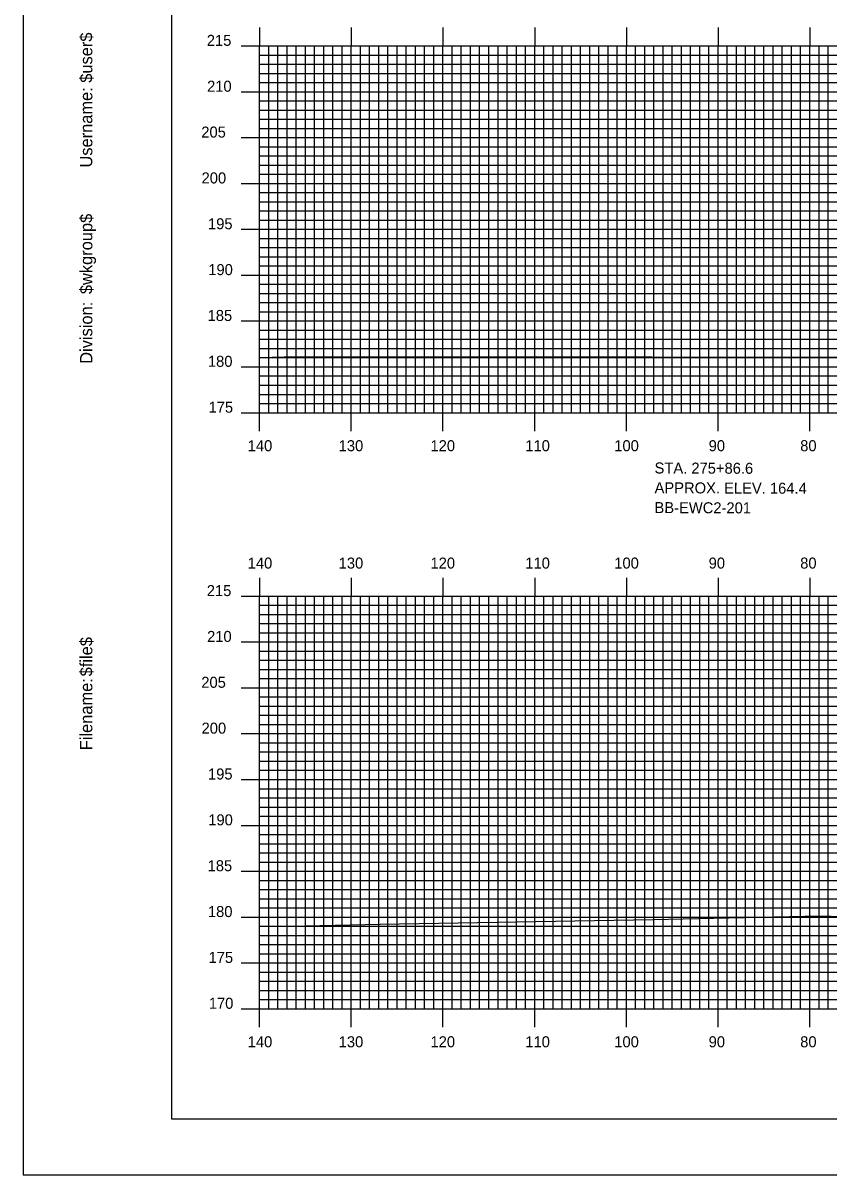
# Model space of a CAD drawing. Extents: x 1809800 to 1810143, y 442591 to 442811.
# Drawn here: x 1809799.6 to 1809887.4, y 442590.5 to 442716.2 of the extents above; entities that cross this region are included whole.
import ezdxf

# ---------------------------------------------------------------- set-up
doc = ezdxf.new("R2010")
doc.units = 0
for name, color, linetype in [('BORDER', 7, 'Continuous'), ('BORING - NO REFUSAL', 7, 'Continuous'), ('H_V ANNOTATION', 7, 'Continuous'), ('MAJOR', 7, 'Continuous'), ('MINOR', 7, 'Continuous'), ('PLOT BOUNDARY', 7, 'Continuous'), ('S_Roadway_Centerline', 7, 'Continuous')]:
    doc.layers.add(name, color=color, linetype=linetype)

msp = doc.modelspace()

# ---------------------------------------------------------------- linework, layer by layer
at = {"layer": 'BORDER'}
msp.add_lwpolyline([(1809815.75, 442596.67), (1810135.75, 442596.67), (1810135.75, 442806.67), (1809815.75, 442806.67)], close=True, dxfattribs=at)
at = {"layer": 'MAJOR'}
for p, q in [((1809825.35, 442715.67), (1809825.35, 442713.67)), ((1809835.35, 442715.67), (1809835.35, 442713.67)), ((1809845.35, 442715.67), (1809845.35, 442713.67)), ((1809855.35, 442715.67), (1809855.35, 442713.67)), ((1809865.35, 442715.67), (1809865.35, 442713.67)), ((1809875.35, 442715.67), (1809875.35, 442713.67)), ((1809885.35, 442715.67), (1809885.35, 442713.67)), ((1809823.35, 442713.67), (1809825.35, 442713.67)), ((1809825.35, 442713.67), (1810105.35, 442713.67)), ((1809825.35, 442673.67), (1809825.35, 442713.67)), ((1809825.35, 442673.67), (1809825.35, 442713.67)), ((1809825.35, 442713.67), (1810105.35, 442713.67)), ((1809835.35, 442673.67), (1809835.35, 442713.67)), ((1809845.35, 442673.67), (1809845.35, 442713.67)), ((1809855.35, 442673.67), (1809855.35, 442713.67)), ((1809865.35, 442673.67), (1809865.35, 442713.67)), ((1809875.35, 442673.67), (1809875.35, 442713.67)), ((1809885.35, 442673.67), (1809885.35, 442713.67)), ((1809823.35, 442708.67), (1809825.35, 442708.67)), ((1809825.35, 442708.67), (1810105.35, 442708.67)), ((1809823.35, 442703.67), (1809825.35, 442703.67)), ((1809825.35, 442703.67), (1810105.35, 442703.67)), ((1809823.35, 442698.67), (1809825.35, 442698.67)), ((1809825.35, 442698.67), (1810105.35, 442698.67)), ((1809823.35, 442693.67), (1809825.35, 442693.67)), ((1809825.35, 442693.67), (1810105.35, 442693.67)), ((1809823.35, 442688.67), (1809825.35, 442688.67)), ((1809825.35, 442688.67), (1810105.35, 442688.67)), ((1809823.35, 442683.67), (1809825.35, 442683.67)), ((1809825.35, 442683.67), (1810105.35, 442683.67)), ((1809823.35, 442678.67), (1809825.35, 442678.67)), ((1809825.35, 442678.67), (1810105.35, 442678.67)), ((1809823.35, 442673.67), (1809825.35, 442673.67)), ((1809825.35, 442673.67), (1810105.35, 442673.67)), ((1809825.35, 442673.67), (1810105.35, 442673.67)), ((1809825.35, 442671.66), (1809825.35, 442673.67)), ((1809835.35, 442671.66), (1809835.35, 442673.67)), ((1809845.35, 442671.66), (1809845.35, 442673.67)), ((1809855.35, 442671.66), (1809855.35, 442673.67)), ((1809865.35, 442671.66), (1809865.35, 442673.67)), ((1809875.35, 442671.66), (1809875.35, 442673.67)), ((1809885.35, 442671.66), (1809885.35, 442673.67)), ((1809825.35, 442655.67), (1809825.35, 442653.67)), ((1809835.35, 442655.67), (1809835.35, 442653.67)), ((1809845.35, 442655.67), (1809845.35, 442653.67)), ((1809855.35, 442655.67), (1809855.35, 442653.67)), ((1809865.35, 442655.67), (1809865.35, 442653.67)), ((1809875.35, 442655.67), (1809875.35, 442653.67)), ((1809885.35, 442655.67), (1809885.35, 442653.67)), ((1809823.35, 442653.67), (1809825.35, 442653.67)), ((1809825.35, 442653.67), (1810105.35, 442653.67)), ((1809825.35, 442608.67), (1809825.35, 442653.67)), ((1809825.35, 442608.67), (1809825.35, 442653.67)), ((1809825.35, 442653.67), (1810105.35, 442653.67)), ((1809835.35, 442608.67), (1809835.35, 442653.67)), ((1809845.35, 442608.67), (1809845.35, 442653.67)), ((1809855.35, 442608.67), (1809855.35, 442653.67)), ((1809865.35, 442608.67), (1809865.35, 442653.67)), ((1809875.35, 442608.67), (1809875.35, 442653.67)), ((1809885.35, 442608.67), (1809885.35, 442653.67)), ((1809823.35, 442648.67), (1809825.35, 442648.67)), ((1809825.35, 442648.67), (1810105.35, 442648.67)), ((1809823.35, 442643.67), (1809825.35, 442643.67)), ((1809825.35, 442643.67), (1810105.35, 442643.67)), ((1809823.35, 442638.67), (1809825.35, 442638.67)), ((1809825.35, 442638.67), (1810105.35, 442638.67)), ((1809823.35, 442633.67), (1809825.35, 442633.67)), ((1809825.35, 442633.67), (1810105.35, 442633.67)), ((1809823.35, 442628.67), (1809825.35, 442628.67)), ((1809825.35, 442628.67), (1810105.35, 442628.67)), ((1809823.35, 442623.67), (1809825.35, 442623.67)), ((1809825.35, 442623.67), (1810105.35, 442623.67)), ((1809823.35, 442618.67), (1809825.35, 442618.67)), ((1809825.35, 442618.67), (1810105.35, 442618.67)), ((1809823.35, 442613.67), (1809825.35, 442613.67)), ((1809825.35, 442613.67), (1810105.35, 442613.67)), ((1809823.35, 442608.67), (1809825.35, 442608.67)), ((1809825.35, 442608.67), (1810105.35, 442608.67)), ((1809825.35, 442608.67), (1810105.35, 442608.67)), ((1809825.35, 442606.66), (1809825.35, 442608.67)), ((1809835.35, 442606.66), (1809835.35, 442608.67)), ((1809845.35, 442606.66), (1809845.35, 442608.67)), ((1809855.35, 442606.66), (1809855.35, 442608.67)), ((1809865.35, 442606.66), (1809865.35, 442608.67)), ((1809875.35, 442606.66), (1809875.35, 442608.67)), ((1809885.35, 442606.66), (1809885.35, 442608.67))]:
    msp.add_line(p, q, dxfattribs=at)
at = {"layer": 'MINOR'}
for p, q in [((1809826.35, 442673.67), (1809826.35, 442713.67)), ((1809827.35, 442673.67), (1809827.35, 442713.67)), ((1809828.35, 442673.67), (1809828.35, 442713.67)), ((1809829.35, 442673.67), (1809829.35, 442713.67)), ((1809830.35, 442673.67), (1809830.35, 442713.67)), ((1809831.35, 442673.67), (1809831.35, 442713.67)), ((1809832.35, 442673.67), (1809832.35, 442713.67)), ((1809833.35, 442673.67), (1809833.35, 442713.67)), ((1809834.35, 442673.67), (1809834.35, 442713.67)), ((1809836.35, 442673.67), (1809836.35, 442713.67)), ((1809837.35, 442673.67), (1809837.35, 442713.67)), ((1809838.35, 442673.67), (1809838.35, 442713.67)), ((1809839.35, 442673.67), (1809839.35, 442713.67)), ((1809840.35, 442673.67), (1809840.35, 442713.67)), ((1809841.35, 442673.67), (1809841.35, 442713.67)), ((1809842.35, 442673.67), (1809842.35, 442713.67)), ((1809843.35, 442673.67), (1809843.35, 442713.67)), ((1809844.35, 442673.67), (1809844.35, 442713.67)), ((1809846.35, 442673.67), (1809846.35, 442713.67)), ((1809847.35, 442673.67), (1809847.35, 442713.67)), ((1809848.35, 442673.67), (1809848.35, 442713.67)), ((1809849.35, 442673.67), (1809849.35, 442713.67)), ((1809850.35, 442673.67), (1809850.35, 442713.67)), ((1809851.35, 442673.67), (1809851.35, 442713.67)), ((1809852.35, 442673.67), (1809852.35, 442713.67)), ((1809853.35, 442673.67), (1809853.35, 442713.67)), ((1809854.35, 442673.67), (1809854.35, 442713.67)), ((1809856.35, 442673.67), (1809856.35, 442713.67)), ((1809857.35, 442673.67), (1809857.35, 442713.67)), ((1809858.35, 442673.67), (1809858.35, 442713.67)), ((1809859.35, 442673.67), (1809859.35, 442713.67)), ((1809860.35, 442673.67), (1809860.35, 442713.67)), ((1809861.35, 442673.67), (1809861.35, 442713.67)), ((1809862.35, 442673.67), (1809862.35, 442713.67)), ((1809863.35, 442673.67), (1809863.35, 442713.67)), ((1809864.35, 442673.67), (1809864.35, 442713.67)), ((1809866.35, 442673.67), (1809866.35, 442713.67)), ((1809867.35, 442673.67), (1809867.35, 442713.67)), ((1809868.35, 442673.67), (1809868.35, 442713.67)), ((1809869.35, 442673.67), (1809869.35, 442713.67)), ((1809870.35, 442673.67), (1809870.35, 442713.67)), ((1809871.35, 442673.67), (1809871.35, 442713.67)), ((1809872.35, 442673.67), (1809872.35, 442713.67)), ((1809873.35, 442673.67), (1809873.35, 442713.67)), ((1809874.35, 442673.67), (1809874.35, 442713.67)), ((1809876.35, 442673.67), (1809876.35, 442713.67)), ((1809877.35, 442673.67), (1809877.35, 442713.67)), ((1809878.35, 442673.67), (1809878.35, 442713.67)), ((1809879.35, 442673.67), (1809879.35, 442713.67)), ((1809880.35, 442673.67), (1809880.35, 442713.67)), ((1809881.35, 442673.67), (1809881.35, 442713.67)), ((1809882.35, 442673.67), (1809882.35, 442713.67)), ((1809883.35, 442673.67), (1809883.35, 442713.67)), ((1809884.35, 442673.67), (1809884.35, 442713.67)), ((1809886.35, 442673.67), (1809886.35, 442713.67)), ((1809887.35, 442673.67), (1809887.35, 442713.67)), ((1809825.35, 442712.67), (1810105.35, 442712.67)), ((1809825.35, 442712.67), (1809827.35, 442712.67)), ((1809825.35, 442711.67), (1810105.35, 442711.67)), ((1809825.35, 442711.67), (1809827.35, 442711.67)), ((1809825.35, 442710.67), (1810105.35, 442710.67)), ((1809825.35, 442710.67), (1809827.35, 442710.67)), ((1809825.35, 442709.67), (1810105.35, 442709.67)), ((1809825.35, 442709.67), (1809827.35, 442709.67)), ((1809825.35, 442707.67), (1810105.35, 442707.67)), ((1809825.35, 442707.67), (1809827.35, 442707.67)), ((1809825.35, 442706.67), (1810105.35, 442706.67)), ((1809825.35, 442706.67), (1809827.35, 442706.67)), ((1809825.35, 442705.67), (1810105.35, 442705.67)), ((1809825.35, 442705.67), (1809827.35, 442705.67)), ((1809825.35, 442704.67), (1810105.35, 442704.67)), ((1809825.35, 442704.67), (1809827.35, 442704.67)), ((1809825.35, 442702.67), (1810105.35, 442702.67)), ((1809825.35, 442702.67), (1809827.35, 442702.67)), ((1809825.35, 442701.67), (1810105.35, 442701.67)), ((1809825.35, 442701.67), (1809827.35, 442701.67)), ((1809825.35, 442700.67), (1810105.35, 442700.67)), ((1809825.35, 442700.67), (1809827.35, 442700.67)), ((1809825.35, 442699.67), (1810105.35, 442699.67)), ((1809825.35, 442699.67), (1809827.35, 442699.67)), ((1809825.35, 442697.67), (1810105.35, 442697.67)), ((1809825.35, 442697.67), (1809827.35, 442697.67)), ((1809825.35, 442696.67), (1810105.35, 442696.67)), ((1809825.35, 442696.67), (1809827.35, 442696.67)), ((1809825.35, 442695.67), (1810105.35, 442695.67)), ((1809825.35, 442695.67), (1809827.35, 442695.67)), ((1809825.35, 442694.67), (1810105.35, 442694.67)), ((1809825.35, 442694.67), (1809827.35, 442694.67)), ((1809825.35, 442692.67), (1810105.35, 442692.67)), ((1809825.35, 442692.67), (1809827.35, 442692.67)), ((1809825.35, 442691.67), (1810105.35, 442691.67)), ((1809825.35, 442691.67), (1809827.35, 442691.67)), ((1809825.35, 442690.67), (1810105.35, 442690.67)), ((1809825.35, 442690.67), (1809827.35, 442690.67)), ((1809825.35, 442689.67), (1810105.35, 442689.67)), ((1809825.35, 442689.67), (1809827.35, 442689.67)), ((1809825.35, 442687.67), (1810105.35, 442687.67)), ((1809825.35, 442687.67), (1809827.35, 442687.67)), ((1809825.35, 442686.67), (1810105.35, 442686.67)), ((1809825.35, 442686.67), (1809827.35, 442686.67)), ((1809825.35, 442685.67), (1810105.35, 442685.67)), ((1809825.35, 442685.67), (1809827.35, 442685.67)), ((1809825.35, 442684.67), (1810105.35, 442684.67)), ((1809825.35, 442684.67), (1809827.35, 442684.67)), ((1809825.35, 442682.67), (1810105.35, 442682.67)), ((1809825.35, 442682.67), (1809827.35, 442682.67)), ((1809825.35, 442681.67), (1810105.35, 442681.67)), ((1809825.35, 442681.67), (1809827.35, 442681.67)), ((1809825.35, 442680.67), (1810105.35, 442680.67)), ((1809825.35, 442680.67), (1809827.35, 442680.67)), ((1809825.35, 442679.67), (1810105.35, 442679.67)), ((1809825.35, 442679.67), (1809827.35, 442679.67)), ((1809825.35, 442677.67), (1810105.35, 442677.67)), ((1809825.35, 442677.67), (1809827.35, 442677.67)), ((1809825.35, 442676.67), (1810105.35, 442676.67)), ((1809825.35, 442676.67), (1809827.35, 442676.67)), ((1809825.35, 442675.67), (1810105.35, 442675.67)), ((1809825.35, 442675.67), (1809827.35, 442675.67)), ((1809825.35, 442674.67), (1810105.35, 442674.67)), ((1809825.35, 442674.67), (1809827.35, 442674.67)), ((1809826.35, 442608.67), (1809826.35, 442653.67)), ((1809827.35, 442608.67), (1809827.35, 442653.67)), ((1809828.35, 442608.67), (1809828.35, 442653.67)), ((1809829.35, 442608.67), (1809829.35, 442653.67)), ((1809830.35, 442608.67), (1809830.35, 442653.67)), ((1809831.35, 442608.67), (1809831.35, 442653.67)), ((1809832.35, 442608.67), (1809832.35, 442653.67)), ((1809833.35, 442608.67), (1809833.35, 442653.67)), ((1809834.35, 442608.67), (1809834.35, 442653.67)), ((1809836.35, 442608.67), (1809836.35, 442653.67)), ((1809837.35, 442608.67), (1809837.35, 442653.67)), ((1809838.35, 442608.67), (1809838.35, 442653.67)), ((1809839.35, 442608.67), (1809839.35, 442653.67)), ((1809840.35, 442608.67), (1809840.35, 442653.67)), ((1809841.35, 442608.67), (1809841.35, 442653.67)), ((1809842.35, 442608.67), (1809842.35, 442653.67)), ((1809843.35, 442608.67), (1809843.35, 442653.67)), ((1809844.35, 442608.67), (1809844.35, 442653.67)), ((1809846.35, 442608.67), (1809846.35, 442653.67)), ((1809847.35, 442608.67), (1809847.35, 442653.67)), ((1809848.35, 442608.67), (1809848.35, 442653.67)), ((1809849.35, 442608.67), (1809849.35, 442653.67)), ((1809850.35, 442608.67), (1809850.35, 442653.67)), ((1809851.35, 442608.67), (1809851.35, 442653.67)), ((1809852.35, 442608.67), (1809852.35, 442653.67)), ((1809853.35, 442608.67), (1809853.35, 442653.67)), ((1809854.35, 442608.67), (1809854.35, 442653.67)), ((1809856.35, 442608.67), (1809856.35, 442653.67)), ((1809857.35, 442608.67), (1809857.35, 442653.67)), ((1809858.35, 442608.67), (1809858.35, 442653.67)), ((1809859.35, 442608.67), (1809859.35, 442653.67)), ((1809860.35, 442608.67), (1809860.35, 442653.67)), ((1809861.35, 442608.67), (1809861.35, 442653.67)), ((1809862.35, 442608.67), (1809862.35, 442653.67)), ((1809863.35, 442608.67), (1809863.35, 442653.67)), ((1809864.35, 442608.67), (1809864.35, 442653.67)), ((1809866.35, 442608.67), (1809866.35, 442653.67)), ((1809867.35, 442608.67), (1809867.35, 442653.67)), ((1809868.35, 442608.67), (1809868.35, 442653.67)), ((1809869.35, 442608.67), (1809869.35, 442653.67)), ((1809870.35, 442608.67), (1809870.35, 442653.67)), ((1809871.35, 442608.67), (1809871.35, 442653.67)), ((1809872.35, 442608.67), (1809872.35, 442653.67)), ((1809873.35, 442608.67), (1809873.35, 442653.67)), ((1809874.35, 442608.67), (1809874.35, 442653.67)), ((1809876.35, 442608.67), (1809876.35, 442653.67)), ((1809877.35, 442608.67), (1809877.35, 442653.67)), ((1809878.35, 442608.67), (1809878.35, 442653.67)), ((1809879.35, 442608.67), (1809879.35, 442653.67)), ((1809880.35, 442608.67), (1809880.35, 442653.67)), ((1809881.35, 442608.67), (1809881.35, 442653.67)), ((1809882.35, 442608.67), (1809882.35, 442653.67)), ((1809883.35, 442608.67), (1809883.35, 442653.67)), ((1809884.35, 442608.67), (1809884.35, 442653.67)), ((1809886.35, 442608.67), (1809886.35, 442653.67)), ((1809887.35, 442608.67), (1809887.35, 442653.67)), ((1809825.35, 442652.67), (1810105.35, 442652.67)), ((1809825.35, 442652.67), (1809827.35, 442652.67)), ((1809825.35, 442651.67), (1810105.35, 442651.67)), ((1809825.35, 442651.67), (1809827.35, 442651.67)), ((1809825.35, 442650.67), (1810105.35, 442650.67)), ((1809825.35, 442650.67), (1809827.35, 442650.67)), ((1809825.35, 442649.67), (1810105.35, 442649.67)), ((1809825.35, 442649.67), (1809827.35, 442649.67)), ((1809825.35, 442647.67), (1810105.35, 442647.67)), ((1809825.35, 442647.67), (1809827.35, 442647.67)), ((1809825.35, 442646.67), (1810105.35, 442646.67)), ((1809825.35, 442646.67), (1809827.35, 442646.67)), ((1809825.35, 442645.67), (1810105.35, 442645.67)), ((1809825.35, 442645.67), (1809827.35, 442645.67)), ((1809825.35, 442644.67), (1810105.35, 442644.67)), ((1809825.35, 442644.67), (1809827.35, 442644.67)), ((1809825.35, 442642.67), (1810105.35, 442642.67)), ((1809825.35, 442642.67), (1809827.35, 442642.67)), ((1809825.35, 442641.67), (1810105.35, 442641.67)), ((1809825.35, 442641.67), (1809827.35, 442641.67)), ((1809825.35, 442640.67), (1810105.35, 442640.67)), ((1809825.35, 442640.67), (1809827.35, 442640.67)), ((1809825.35, 442639.67), (1810105.35, 442639.67)), ((1809825.35, 442639.67), (1809827.35, 442639.67)), ((1809825.35, 442637.67), (1810105.35, 442637.67)), ((1809825.35, 442637.67), (1809827.35, 442637.67)), ((1809825.35, 442636.67), (1810105.35, 442636.67)), ((1809825.35, 442636.67), (1809827.35, 442636.67)), ((1809825.35, 442635.67), (1810105.35, 442635.67)), ((1809825.35, 442635.67), (1809827.35, 442635.67)), ((1809825.35, 442634.67), (1810105.35, 442634.67)), ((1809825.35, 442634.67), (1809827.35, 442634.67)), ((1809825.35, 442632.67), (1810105.35, 442632.67)), ((1809825.35, 442632.67), (1809827.35, 442632.67)), ((1809825.35, 442631.67), (1810105.35, 442631.67)), ((1809825.35, 442631.67), (1809827.35, 442631.67)), ((1809825.35, 442630.67), (1810105.35, 442630.67)), ((1809825.35, 442630.67), (1809827.35, 442630.67)), ((1809825.35, 442629.67), (1810105.35, 442629.67)), ((1809825.35, 442629.67), (1809827.35, 442629.67)), ((1809825.35, 442627.67), (1810105.35, 442627.67)), ((1809825.35, 442627.67), (1809827.35, 442627.67)), ((1809825.35, 442626.67), (1810105.35, 442626.67)), ((1809825.35, 442626.67), (1809827.35, 442626.67)), ((1809825.35, 442625.67), (1810105.35, 442625.67)), ((1809825.35, 442625.67), (1809827.35, 442625.67)), ((1809825.35, 442624.67), (1810105.35, 442624.67)), ((1809825.35, 442624.67), (1809827.35, 442624.67)), ((1809825.35, 442622.67), (1810105.35, 442622.67)), ((1809825.35, 442622.67), (1809827.35, 442622.67)), ((1809825.35, 442621.67), (1810105.35, 442621.67)), ((1809825.35, 442621.67), (1809827.35, 442621.67)), ((1809825.35, 442620.67), (1810105.35, 442620.67)), ((1809825.35, 442620.67), (1809827.35, 442620.67)), ((1809825.35, 442619.67), (1810105.35, 442619.67)), ((1809825.35, 442619.67), (1809827.35, 442619.67)), ((1809825.35, 442617.67), (1810105.35, 442617.67)), ((1809825.35, 442617.67), (1809827.35, 442617.67)), ((1809825.35, 442616.67), (1810105.35, 442616.67)), ((1809825.35, 442616.67), (1809827.35, 442616.67)), ((1809825.35, 442615.67), (1810105.35, 442615.67)), ((1809825.35, 442615.67), (1809827.35, 442615.67)), ((1809825.35, 442614.67), (1810105.35, 442614.67)), ((1809825.35, 442614.67), (1809827.35, 442614.67)), ((1809825.35, 442612.67), (1810105.35, 442612.67)), ((1809825.35, 442612.67), (1809827.35, 442612.67)), ((1809825.35, 442611.67), (1810105.35, 442611.67)), ((1809825.35, 442611.67), (1809827.35, 442611.67)), ((1809825.35, 442610.67), (1810105.35, 442610.67)), ((1809825.35, 442610.67), (1809827.35, 442610.67)), ((1809825.35, 442609.67), (1810105.35, 442609.67)), ((1809825.35, 442609.67), (1809827.35, 442609.67))]:
    msp.add_line(p, q, dxfattribs=at)
at = {"layer": 'PLOT BOUNDARY'}
msp.add_lwpolyline([(1809799.56, 442590.55), (1810139.56, 442590.55), (1810139.56, 442810.55), (1809799.56, 442810.55)], close=True, dxfattribs=at)
at = {"layer": 'S_Roadway_Centerline'}
for points in [[(1809825.35, 442679.7), (1809828.05, 442679.76), (1809855.59, 442679.8), (1809880.69, 442679.71), (1809893.54, 442679.73), (1809898.83, 442679.95), (1809917.98, 442680.22), (1809923.05, 442680.39), (1809926.25, 442680.29), (1809946.9, 442680.16), (1809966.91, 442680.36), (1809968.11, 442680.37), (1809968.22, 442680.37), (1809968.35, 442680.37), (1809981.34, 442680.67), (1809992.14, 442680.28), (1809993.93, 442680.26), (1810003.99, 442680.43)], [(1809825.35, 442617.68), (1809830.33, 442617.73), (1809838.49, 442617.91), (1809868.24, 442618.39), (1809884.81, 442618.77), (1809887.68, 442618.75), (1809897.53, 442618.7), (1809921.01, 442618.91), (1809956.01, 442619.3), (1809959.39, 442619.17), (1809963.41, 442619.2), (1809991.29, 442619.23), (1810016.11, 442618.63), (1810025.9, 442618.65), (1810059.8, 442618.6), (1810084.68, 442618.68), (1810098.88, 442619.31), (1810105.35, 442619.22)]]:
    msp.add_lwpolyline(points, dxfattribs=at)

# ---------------------------------------------------------------- texts
at = {"layer": 'BORDER'}
for s, p in [('$user$', (1809807.12, 442709.65)), ('Username:', (1809807.12, 442700.4)), ('$wkgroup$', (1809807.12, 442686.6)), ('Division:', (1809807.12, 442679)), ('$file$', (1809807.12, 442644.92)), ('Filename:', (1809807.12, 442636.86))]:
    msp.add_text(s, height=1.339, rotation=90, dxfattribs=at).set_placement(p)
at = {"layer": 'BORING - NO REFUSAL'}
for s, p in [('STA. 275+86.6', (1809868.42, 442667.04)), ('APPROX. ELEV. 164.4', (1809868.42, 442664.88)), ('BB-EWC2-201', (1809868.41, 442662.72))]:
    msp.add_text(s, height=1.2, rotation=359.8142, dxfattribs=at).set_placement(p)
at = {"layer": 'H_V ANNOTATION'}
for s, p in [('215', (1809819.6, 442713.67)), ('210', (1809819.63, 442708.67)), ('205', (1809819, 442703.67)), ('200', (1809819.03, 442698.67)), ('195', (1809819.73, 442693.67)), ('190', (1809819.76, 442688.67)), ('185', (1809819.69, 442683.67)), ('180', (1809819.72, 442678.67)), ('175', (1809819.79, 442673.67)), ('140', (1809824.06, 442669.47)), ('130', (1809833.98, 442669.47)), ('120', (1809843.99, 442669.47)), ('110', (1809854.33, 442669.47)), ('100', (1809864.03, 442669.47)), ('90', (1809874.32, 442669.47)), ('80', (1809884.3, 442669.47)), ('140', (1809824.06, 442656.67)), ('130', (1809833.98, 442656.67)), ('120', (1809843.99, 442656.67)), ('110', (1809854.33, 442656.67)), ('100', (1809864.03, 442656.67)), ('90', (1809874.32, 442656.67)), ('80', (1809884.3, 442656.67)), ('215', (1809819.6, 442653.67)), ('210', (1809819.63, 442648.67)), ('205', (1809819, 442643.67)), ('200', (1809819.03, 442638.67)), ('195', (1809819.73, 442633.67)), ('190', (1809819.76, 442628.67)), ('185', (1809819.69, 442623.67)), ('180', (1809819.72, 442618.67)), ('175', (1809819.79, 442613.67)), ('170', (1809819.82, 442608.67)), ('140', (1809824.06, 442604.47)), ('130', (1809833.98, 442604.47)), ('120', (1809843.99, 442604.47)), ('110', (1809854.33, 442604.47)), ('100', (1809864.03, 442604.47)), ('90', (1809874.32, 442604.47)), ('80', (1809884.3, 442604.47))]:
    msp.add_text(s, height=1.2, dxfattribs=at).set_placement(p)
at = {"layer": 'MAJOR'}
for p in [(1809825.34, 442673.67), (1809825.34, 442608.67)]:
    msp.add_text('-', height=0.012, dxfattribs=at).set_placement(p)

doc.saveas('drawing.dxf')
